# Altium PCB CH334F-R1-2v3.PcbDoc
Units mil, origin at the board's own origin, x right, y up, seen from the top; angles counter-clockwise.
Board outline 3110.24 x 866.14 mil, 2 copper layers (Top Layer, Bottom Layer); 18 components, 20 nets, 108 pads, 313 vias.
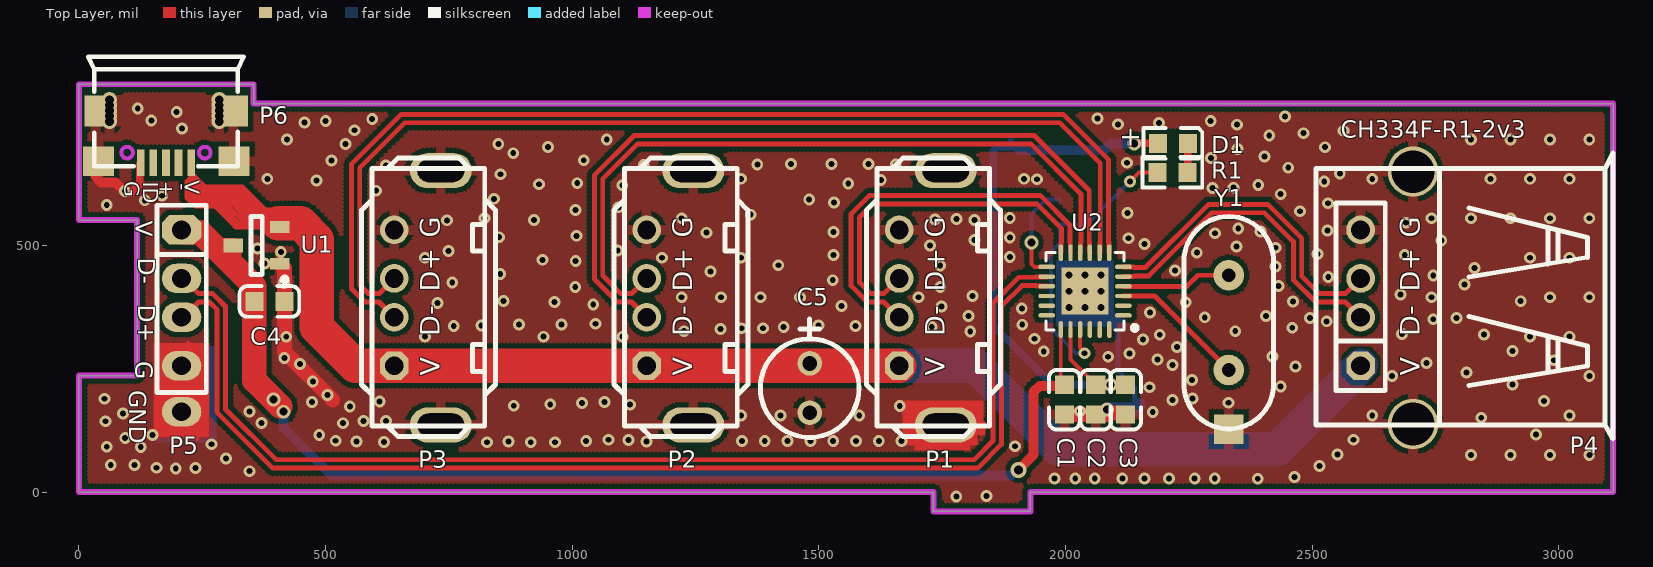
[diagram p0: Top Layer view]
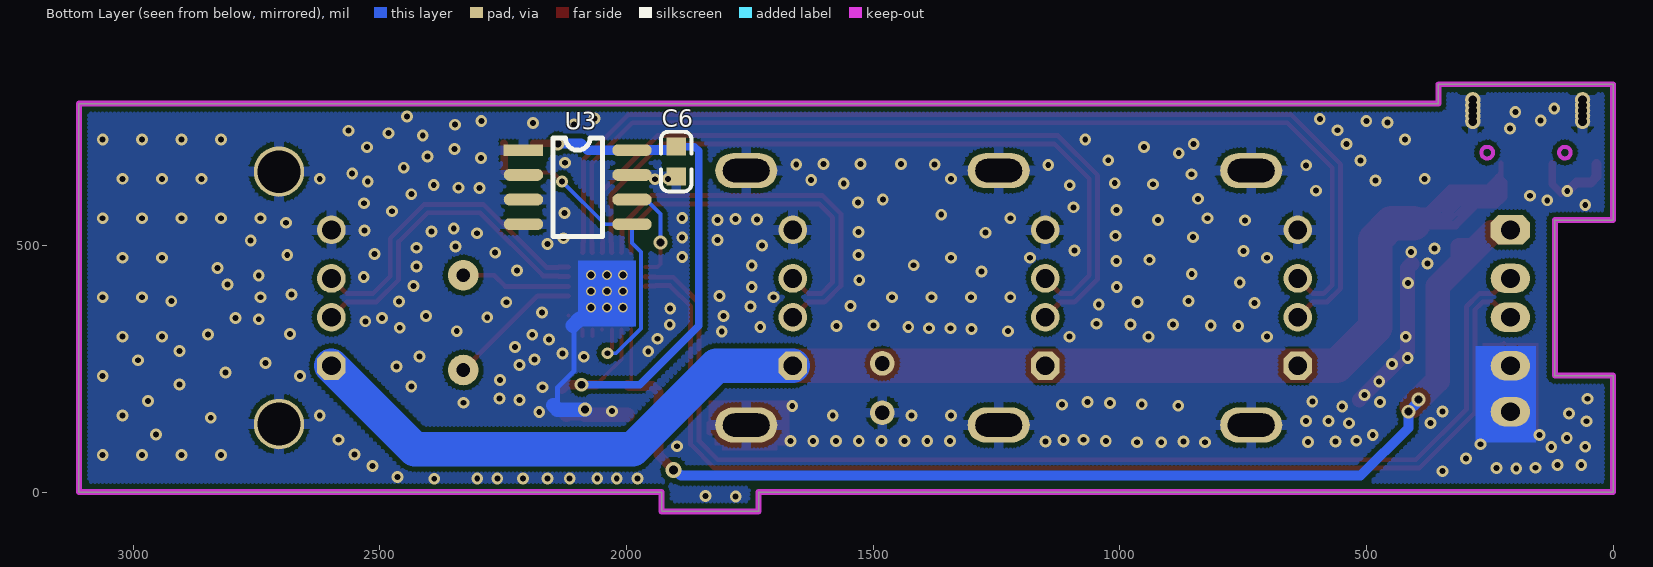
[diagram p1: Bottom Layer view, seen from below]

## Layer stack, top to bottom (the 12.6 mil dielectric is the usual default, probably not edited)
Top Solder: solder mask 0.4, Solder Resist, Dk 3.5
Top Layer: signal copper 1.4
Dielectric 1: dielectric 12.6, FR-4, Dk 4.8
Bottom Layer: signal copper 1.4
Bottom Solder: solder mask 0.4, Solder Resist, Dk 3.5

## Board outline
0,0 0,236.22 118.11,236.22 118.11,551.18 0,551.18 0,826.77 354.33,826.77 354.33,787.4 3110.24,787.4 3110.24,0 1929.13,0 1929.13,-39.37 1732.28,-39.37 1732.28,0

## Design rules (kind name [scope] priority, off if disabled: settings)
Clearance Clearance_1 [InPolygon] p1: gap=10 ignorepadtopadclearanceinfootprint=FALSE
Clearance [All] p2: gap=6 ignorepadtopadclearanceinfootprint=FALSE except(8: Arc-Via Track-Via SMDPad-Via THPad-Via Via-Via Via-Fill Via-Poly Via-Region Via-Hole)
ComponentClearance [All] p1 off: gap=10 collisioncheckmode=3 verticalgap=10 showdistances=FALSE
DiffPairsRouting [All] p1: maxlimit=10 minlimit=7 mostfreqgap=8 toplayer_minwidth=6 toplayer_maxwidth=15 toplayer_prefwidth=8 bottomlayer_minwidth=6 bottomlayer_maxwidth=15 bottomlayer_prefwidth=8 maxuncoupledlength=500
MinimumSolderMaskSliver [All] p1 off: minsoldermaskwidth=10
PolygonConnect PolygonConnect_1 [IsVia] p1: connectstyle=Direct reliefconductorwidth=10 reliefentries=4 polygonreliefangle="90 Angle" airgapwidth=10
PolygonConnect [All] p2: connectstyle=Relief reliefconductorwidth=20 reliefentries=4 polygonreliefangle="90 Angle" airgapwidth=10
RoutingVias [All] p1: holewidth=16 width=28 viastyle="Through Hole" minholewidth=12 minwidth=24 maxholewidth=28 maxwidth=50
SilkToSilkClearance [All] p1 off: silktosilkclearance=10
SilkToSolderMaskClearance [IsPad] p1 off: minsilkscreentomaskgap=10 clearancetoexposedcopper=TRUE
SolderMaskExpansion [All] p1: expansion=4 istentingtop=FALSE
Width [All] p1: maxlimit=100 minlimit=6 preferedwidth=10
25 further rules are at their usual default settings.

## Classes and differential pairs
differential pair UD: +UD_p -UD_n
differential pair UD4: +UD4_p -UD4_n
differential pair UD3: +UD3_p -UD3_n
differential pair UD2: +UD2_p -UD2_n
differential pair UD1: +UD1_p -UD1_n

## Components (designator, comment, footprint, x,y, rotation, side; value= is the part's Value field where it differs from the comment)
C1 "1uF" 0603_C 1997.81,217.54 r270 top
C2 "0.1uF" 0603_C 2061.45,217.54 r270 top
C3 "10uF" 0603_C 2121.9,217.54 r270 top
C4 "10uF" 0603_C 356.1,386.39 r0 top
C5 "220uF" CD0.1 1481.53,260.82 r270 top
C6 "NC(1uF)" 0603_C 1899.27,700.37 r270 bottom
D1 "LED" 0603+ 2188.05,706.74 r0 top
P1 "USB" USB2.0-A-F-TH_4P-V_13.7mm 1662.83,255.91 r180 top
P2 "USB" USB2.0-A-F-TH_4P-V_13.7mm 1151.02,255.91 r180 top
P3 "USB" USB2.0-A-F-TH_4P-V_13.7mm 639.21,255.91 r180 top
P4 "USB" USBAF#1 2598.25,255.91 r90 top
P5 "USB" USBAF#2 208.21,531.5 r270 top
P6 "PowerSupply" USBMICROB-02-GXPX-A1T2 227.66,667.45 r180 top
R1 "1K" 0603_R 2216.99,648.17 r0 top
U1 "CH213K" SOT-23-3 407.15,462.5 r90 top
U2 "CH334F" QFN24_4X4 2039.71,407.29 r90 top
U3 "NC(24C02)" SOIC-8_150mil 2208.98,692.96 r270 bottom
Y1 "12M" XT_AT49 2330.98,247.39 r0 top

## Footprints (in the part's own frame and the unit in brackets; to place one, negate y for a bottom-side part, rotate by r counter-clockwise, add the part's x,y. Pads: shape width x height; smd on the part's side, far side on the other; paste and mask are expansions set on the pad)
0603+ [mm]
  rect 0.93x0.98 smd: 1(0,0) 2(1.54,0)
  silkscreen extent -0.76,-0.79 2.27,0.79
0603_C [mm]
  rect 0.93x0.98 smd: 1(0,0) 2(1.54,0)
  silkscreen extent -0.76,-0.79 2.31,0.79
0603_R [mm]
  rect 0.93x0.98 smd: 1(-0.77,0) 2(0.77,0)
  silkscreen extent -1.53,-0.79 1.54,0.79
CD0.1 [mil]
  round 50 hole 30: 1(0,0) 2(100,0)
  silkscreen extent -90,-100 150,100
QFN24_4X4 [mil]
  round 20 hole 14: 0(-33.21,-32.4) 0(-33.21,32.2) 0(-0.21,-0.1) 0(32.79,-32.4) 0(32.79,32.2)
  rect 95x95 smd mask+2: 0(0,0)
  oval 9x34 smd mask+2: 1(-49.21,-77.8) 2(-29.53,-77.8) 3(-9.84,-77.8) 4(9.84,-77.8) 5(29.53,-77.8) 6(49.21,-77.8) 13(49.21,77.8) 14(29.53,77.8) 15(9.84,77.8) 16(-9.84,77.8) 17(-29.53,77.8) 18(-49.21,77.8)
  oval 34x9 smd mask+2: 7(77.8,-49.21) 8(77.8,-29.53) 9(77.8,-9.84) 10(77.8,9.84) 11(77.8,29.53) 12(77.8,49.21) 19(-77.8,49.21) 20(-77.8,29.53) 21(-77.8,9.84) 22(-77.8,-9.84) 23(-77.8,-29.53) 24(-77.8,-49.21)
  silkscreen extent -79,-106 78,79
SOIC-8_150mil [mil]
  rect 24x80 smd: 1(0,0)
  oval 24x80 smd: 2(50,0) 3(100,0) 4(150,0) 5(150,220) 6(100,220) 7(50,220) 8(0,220)
  silkscreen extent -25,60 175,160
SOT-23-3 [mm] "SOT-23-3"
  rect 0.6x1 smd: 1(0,0) 2(1.9,0)
  rect 0.7x1 smd: 3(0.95,2.4)
  silkscreen extent -0.93,-0.38 2.45,1.49
USB2.0-A-F-TH_4P-V_13.7mm [mm]
  oval 3.2x1.8 hole 1.2 slot 2.4 at 0 deg: 0(-2.4,3.05) 0(-2.4,-10.05)
  oct 1.473x1.473 hole 0.965: 1(0,0)
  round 1.473 hole 0.965: 2(0,-2.5) 3(0,-4.5) 4(0,-7)
  silkscreen extent -5.21,-10.71 1.69,3.65
USBAF#1 [mm]
  round 2.6 hole 2.2: 0(-3,-2.7) 0(10,-2.7)
  oct 1.473x1.473 hole 0.965: 1(0,0)
  round 1.473 hole 0.965: 2(2.5,0) 3(4.5,0) 4(7,0)
  silkscreen extent -3.75,-12.99 10.95,2.29
USBAF#2 [mm]
  oct 1.524x2.032 hole 0.965: 1(0,0)
  oval 1.524x2.032 hole 0.965: 2(2.5,0) 3(4.5,0) 4(7,0)
  silkscreen extent -1.27,-1.27 8.38,1.27
USBMICROB-02-GXPX-A1T2 [mm]
  rect 1.6x1.5 smd: 0(-2.203,-0.083) 0(4.769,-0.083)
  rect 1.5x1.6 smd: 0(-2.167,-2.675)
  round 0.8 hole 0.45: 0(-1.442,-2.134) 0(-1.442,-3.243) 0(-1.442,-2.966) 0(-1.442,-2.689) 0(-1.442,-2.411) 0(4.208,-2.689) 0(4.208,-2.411) 0(4.208,-2.134) 0(4.208,-3.243) 0(4.208,-2.966)
  rect 1.1x1.6 smd: 0(4.933,-2.675)
  rect 0.4x1.35 smd mask+0.051: 1(0,0) 2(0.65,0) 3(1.3,0) 4(1.95,0) 5(2.6,0)
  Keep-Out Layer circle w0.203: c3.3,-0.525 r0.3
  Keep-Out Layer circle w0.203: c-0.7,-0.525 r0.3
  silkscreen extent -2.7,-5.46 5.3,0.17
XT_AT49 [mil]
  rect 60x60 smd: 0(0.03,-119.99)
  round 62 hole 28: 1(0,0) 2(0,192.13)
  silkscreen extent -91,-119 91,311

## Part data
C1 C2 C3 C4 C5 C6: library part CAP, "Capacitor"
D1: "Typical INFRARED GaAs LED"
P1 P2 P3 P4 P5: "USB Port"
P6: library part MicroUSB, "MicroUSB Port"
R1: library part RES
U1: "Ideal Diode 5V*1A"
U2: "4 ports High-Speed USB MTT Hub with over current detect & power control"
U3: library part 24C01
Y1: library part XTAL, "Crystal Oscillator"

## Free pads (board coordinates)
  oval 80x60 hole 38: ""(208.21,162.81)

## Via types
v1: diameter 24, hole 12, Top Layer to Bottom Layer, tented both sides, 302 vias
v2: diameter 28, hole 16, Top Layer to Bottom Layer, tented both sides, 6 vias
v3: diameter 20, hole 14, Top Layer to Bottom Layer, tented both sides, 4 vias
v4: diameter 32, hole 18, Top Layer to Bottom Layer, tented both sides, 1 vias

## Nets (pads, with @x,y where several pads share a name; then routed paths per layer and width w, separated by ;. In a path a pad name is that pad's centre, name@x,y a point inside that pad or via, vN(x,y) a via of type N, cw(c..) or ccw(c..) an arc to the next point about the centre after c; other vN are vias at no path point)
3V3: C2.1 C3.1 C6.1 D1.1 U2.20 U3.8 | length 1212.2
  Top Layer w8: U2.20 2010.37,329.29 2010.37,268.62 2046.15,232.84 2046.15,231.85 C2.1@2047.14,231.85 ; C2.1@2047.14,231.85 C2.1 C2.1@2047.14,231.85
  Top Layer w15: v2(2139.55,706.74) D1.1
  Top Layer w20: C2.1 v2(2091.61,217.54) C3.1 C3.1@2130.21,209.24
  Bottom Layer w15: C6.1@1888.78,709.88 1888.78,701.67 1887.48,700.37 1862.32,700.37 1853.53,691.59 1853.53,336.86 1972.85,217.54 v2(2091.61,217.54)
  Bottom Layer w20: C6.1 1905.92,693.72 1957.39,693.72 U3.8@1987.9,693.72 ; U3.8 2078.06,692.96 2091.84,706.74 v2(2139.55,706.74)
5V: C1.1 C4.1 P5.1 U1.3 U2.19 | length 2493.6
  Top Layer w8: U2.19 1990.5,224.86 C1.1
  Top Layer w20: v2(415,163) 415.37,163 v2@422.95,170.59 ; v4(1905,45) 1935.54,75.54 1935.54,203.42 1947.25,215.13 1995.4,215.13 C1.1
  Top Layer w30: 282.85,499.91 U1.3 313.69,499.9 314.91,498.68 314.91,463.33
  Top Layer w50: P5.1 212.86,526.85 246.01,526.85 355.63,417.23 355.63,226.31 v2@407.93,174.01
  Bottom Layer w20: v2(394.44,187.5) 395.97,185.97 395.97,182.03 v2(415,163) 415,130.2 511.85,33.35 1890.1,33.35 1901.75,45 v4(1905,45)
GND: C1.2 C2.2 C3.2 C4.2 C5.2 C6.2 P1.0 P1.4 P2.0 P2.4 P3.0 P3.4 P4.0 P4.4 P5.4 P6.0 P6.5 pad. U1.1 U2.0 U3.1 U3.2 U3.3 U3.4 U3.7 Y1.0 | length 1884.7
  Top Layer w8: 220.81,208.41 220.81,302.53 ; 222,112.53 222,206.65 ; 225,112.53 225,206.65 ; 227.09,204.87 227.09,299 ; 230,111.08 230,205.21 ; 233,204.17 233,298.3 ; 234,111.08 234,205.21 ; 240,107.99 240,295.21 ; 1834.11,119.74 1834.11,140.29
  Top Layer w15: 104.84,605.5 123.71,624.36 P6.5@123.71,665.85
  Top Layer w20: P6.0@33.46,665 33.46,639.41 45.12,627.76 74.35,627.76 91.94,610.17 v1(93.02,610.17)
  Top Layer w30: U1.1 408.65,462.5 416.73,454.42 C4.2 416.73,284.82 514.65,186.9 ; C1.2 C2.2 v2@2083.96,156.91 ; v2@2083.96,160.06 2118.76,160.06 C3.2
  Bottom Layer w10: U2.0@2039.78,402.6 2072.11,370.27 2091.54,350.84 2106.8,335.58 2106.8,245.19 2139.81,212.19 2139.81,167.06 ; v2(2083.96,167.06) v2@2083.96,169.37
  Bottom Layer w30: U2.0@2072.11,374.08 2072.11,370.27 2072.11,362.52 2083.79,350.84 2091.54,350.84 2095.35,350.84 2108.7,337.49 ; v2(2083.96,167.06) 2139.81,167.06 2148.69,175.95
  other v1: 1778.73,-8.71 1840.22,-8.03 2389.86,26.95 1977.78,27.84 2019.86,27.84 2059.43,27.84 2115.25,27.84 2160.41,27.84 2210.19,27.84 2262,27.84 2302.63,27.84 2464.24,30.58 345.77,42.29 196.36,47.86 157.58,49.29 236.59,48.81 2514.7,52.91 64.67,55.04 112.56,54.56 298,68.06 2822,75 2902,75 2982,75 3062,75 2551.51,75.81 125.49,91.43 56.53,91.91 1897.91,92.85 269.09,96.97 618.87,101.5 827.57,100.98 916.07,100.98 965.42,100.98 563.05,102.8 870.97,102.68 1150.93,102.68 1344.12,103.19 1390.38,103.19 1436.63,103.19 1482.89,103.19 1529.14,103.19 1575.4,103.19 1621.65,103.19 1667.91,103.19 520.64,104.1 1028.39,103.53 1114.34,105.23 1073.49,106.08 2584.23,106.08 93.89,109.63 149.43,115.38 487.31,115.35 2953.66,116.98 370.18,139.83 535.35,139.58 54.14,143.63 576.89,143.91 622.77,143.91 2842.89,150.73 1342,155 1422,155 1582,155 2622,155 3022,155 89.58,159.43 2176.96,162.23 345.61,163.53 2029.63,163.91 549.2,173.34 1664.05,174.13 881.63,174.96 1117.55,177.16 955.63,177.89 1020.11,180.82 2330.39,181.01 1065.53,182.28 472.28,182.92 609.78,183.72 2970.04,184.47 2216.8,186.53 51.74,189.12 2257.28,189.87 504.33,197.02 2170.22,212.45 2436.35,213.77 2906.47,218.22 474.21,223.93 2256.41,227.06 2662,235 3062,235 2813.04,242.58 2466.61,254.53 2216.8,257.36 448.57,259.82 2732.05,261.79 2990.27,267.24 2186.83,268.8 416.43,271.67 2086.65,274.28 2419.56,275.03 2129.63,280.79 1956.07,285.3 2906.47,285.71 2226.06,294.41 2157.41,309.12 1937.53,310.77 420.38,314.93 702,315 942,315 1102,315 2942,315 3022,315 2191.2,318.87 2848.67,319.45 2681.97,320.55 1226.76,326.1 1807.05,325.77 2344.2,326.16 1300.83,330.59 1343.48,332.09 1386.87,332.09 2459.82,333.02 1428.77,334.33 1729.02,334.29 760.01,336.88 1574.67,336.58 815.69,337.61 1499.1,338.08 1912.34,339.28 891.89,339.81 978.34,339.81 1047.21,341.27 2529.59,346.11 2745.54,350.41 2495.56,353.03 2792.74,353.2 2282.31,354.29 1803.79,356.93 2406.72,357.22 2171.5,363.82 1911.51,371.94 1749.02,376.08 1545.74,376.85 1042.82,380.11 727.04,383.04 964.42,385.23 2243.73,384.83 2461.54,386.48 861.12,387.43 2922.84,386.94 1222,395 1302,395 1382,395 1462,395 1702,395 2742,395 2982,395 3062,395 1811.48,397.65 2679.08,400.49 1006.25,415.39 1746.14,415.53 2431.86,417.55 2809.11,420.69 415.57,423.72 756.97,424.97 1528.18,429.51 2532.67,435.86 2745.54,439.02 854.15,442.08 1280.14,447.3 2221.76,448.89 2829.34,454.43 2425.93,456.98 1746.14,459.32 1417.86,459.82 376.59,463.37 1007.16,468.13 939.67,470.84 702,475 1182,475 1342,475 2942,475 3022,475 1887.16,476.48 2687.75,480.44 1529.98,480.68 2511.25,482.86 2266.27,485.27 409.35,486.84 749.2,488.72 1092.03,489.51 362.14,494.06 2425.93,495.35 2346.44,497.74 1725.48,499.88 2160.48,502.83 2761.91,510.3 1815.86,510.79 2128.08,514.59 1887.16,515.96 851.82,516.71 1009,519.49 2303.13,524.72 1272.17,525.84 1529.98,527.32 2395.58,528 2531.26,530.47 2350.37,534.58 2690.64,545.94 746.09,550.91 922.56,551.69 1735.63,552.2 1815.86,551.8 1779.03,553.42 822,555 1222,555 1887.16,555.45 2742,555 2822,555 2902,555 2982,555 3062,555 1362.09,562.26 2125.62,565.59 2475.17,569.23 1006.71,571.47 1093.71,577.24 56.52,582.14 2531.95,585.51 1530.58,587.28 133.59,591.4 1480.46,592.99 841.71,594.45 168.18,600.66 2436.36,603.88 602.29,610.91 2297.76,616.36 2340.73,617.05 1101.53,621.94 2390.91,622.82 932.67,623.99 1559.66,625.44 1010.25,626.12 2524.65,629.78 481.91,631.79 1625.68,632.71 1941.98,634.08 382,635 1342,635 1916.16,635 2622,635 2862,635 2942,635 3022,635 854.93,644.21 2556.15,645.98 2451.69,657.58 622.24,662.42 1145.12,662.73 1375.3,663.89 1655.97,663.89 1443.81,664.72 1525.54,664.72 1600.66,664.72 2124.57,667.64 512.24,672.46 1023.41,672.66 2295.1,677.34 2403.5,680.53 880.58,686.96 2348.53,695.62 951.33,699.4 2526.2,699.11 540.34,705.78 850.26,705.62 422,715 1070.19,714.85 2822,715 2902,715 2982,715 3062,715 2413.15,722.66 2482.48,727.5 559.03,733.42 2563.44,732.6 209.17,737.14 2348.1,744.74 2106.8,745.52 2189.58,748.45 457.39,749.48 500.31,752.44 2294.4,752.41 146.87,753.14 594.64,756.14 2064.71,756.96 2444.72,761.4 198.29,770.28 119.32,777.75
  other v3: 2039.81,374.08 2007.51,407.08 2072.11,407.08 2039.81,440.08
NetD1_2: D1.2 R1.2 | length 59.1
  Top Layer w15: R1.2 2247.99,648.86 2247.99,706.05 D1.2
NetU2_3: U2.3 Y1.1 | length 275.6
  Top Layer w10: U2.3 2180.93,397.45 Y1.1
NetU2_4: U2.4 Y1.2 | length 222.7
  Top Layer w10: U2.4 2246.22,417.13 2268.61,439.52 Y1.2
RST: U2.16
SCL: U2.13 U3.6 | length 203.7
  Top Layer w8: v2(1931.4,505.84) 1931.4,462.49 1937.39,456.5 U2.13
  Bottom Layer w8: v2(1931.4,505.84) 1931.4,563.4 1960.95,592.96 U3.6
SDA: R1.1 U2.21 U3.5 | length 600.3
  Top Layer w8: U2.21 2029.87,291.74 2038.5,283.11 2038.45,283.06 v1(2038.45,281.4) ; v1(2130.65,629.85) 2148.96,648.17 R1.1
  Bottom Layer w8: v1(2038.45,281.4) 2021.06,281.4 1970.77,331.7 1970.77,486.9 1988.98,505.11 U3.5 2043.75,542.96 v1(2130.65,629.85)
UD1_n: P1.2 U2.11 | length 810.3
  Top Layer w10: P1.2 1631.96,385.2 1598.32,385.2 1565.48,418.04 1565.48,563.91 1602.93,601.37 1949,601.37 2008.84,541.53 2008.84,506.83 2009.68,505.98 2009.68,485.59 U2.11
UD1_p: P1.3 U2.12 | length 725.8
  Top Layer w10: P1.3 1631.96,402.2 1605.36,402.2 1582.48,425.09 1582.48,556.87 1609.97,584.37 1941.96,584.37 1991.84,534.48 1991.84,506.83 1991,505.98 1991,485.59 U2.12
UD2_n: P2.2 U2.9 | length 1557.8
  Top Layer w10: P2.2 1120.15,385.2 1091.69,385.2 1045,431.89 1045,642.04 1125.69,722.73 1936.76,722.73 2048.21,611.28 2048.21,506.83 2049.05,505.98 2049.05,485.59 U2.9
UD2_p: P2.3 U2.10 | length 1473.3
  Top Layer w10: P2.3 1120.15,402.2 1098.73,402.2 1062,438.93 1062,635 1132.73,705.73 1929.72,705.73 2031.21,604.24 2031.21,506.83 2030.37,505.98 2030.37,485.59 U2.10
UD3_n: P3.2 U2.7 | length 2166.8
  Top Layer w10: P3.2 608.34,385.2 579.97,385.2 552.41,412.76 552.41,664.45 653.57,765.61 1995.3,765.61 2087.58,673.33 2087.58,506.83 2088.42,505.98 2088.42,485.59 U2.7
UD3_p: P3.3 U2.8 | length 2082.3
  Top Layer w10: P3.3 608.34,402.2 587.01,402.2 569.41,419.8 569.41,657.41 660.61,748.61 1988.25,748.61 2070.58,666.28 2070.58,506.83 2069.74,505.98 2069.74,485.59 U2.8
UD4_n: P4.2 U2.5 | length 667.4
  Top Layer w10: U2.5 2118.01,437.32 2138.41,437.32 2139.25,438.16 2169.12,438.16 2297.19,566.23 2403.34,566.23 2462.04,507.54 2462.04,430.28 2507.11,385.2 2567.38,385.2 P4.2
UD4_p: P4.3 U2.6 | length 667.4
  Top Layer w10: U2.6 2118.01,456 2138.41,456 2139.25,455.16 2162.08,455.16 2290.15,583.23 2410.39,583.23 2479.04,514.58 2479.04,437.32 2514.15,402.2 2567.38,402.2 P4.3
UD_n: P5.2 U2.14 | length 2345.5
  Top Layer w10: P5.2 211.83,433.07 242.7,402.2 271.31,402.2 297.25,376.26 297.25,168.13 399.94,65.44 1814.85,65.44 1853.11,103.71 1853.11,383.37 1905.21,435.47 1940.17,435.47 1941.02,436.32 1961.41,436.32 U2.14
UD_p: P5.3 U2.15 | length 2345.5
  Top Layer w10: P5.3 211.83,354.33 242.7,385.2 264.27,385.2 280.25,369.22 280.25,161.09 392.9,48.44 1821.89,48.44 1870.11,96.67 1870.11,376.33 1912.25,418.47 1940.17,418.47 1941.02,417.63 1961.41,417.63 U2.15
VBUS: C5.1 P1.1 P2.1 P3.1 P4.1 P6.1 U1.2 | length 4419.3
  Top Layer w10: 247.13,591.38 252.13,591.38 ; 252.85,603.63 251.45,605.02 ; 252.85,608.63 252.85,605.02 ; 254.37,584.14 259.37,584.14 ; 339.62,561.86 345.62,561.86 ; U1.2@404.02,544.78 336.98,544.78 ; 404.02,553.86 340.88,553.86 310.6,584.14 259.37,584.14 ; U1.2 318.44,537.3 310.96,544.78 ; 407.15,571.39 378.91,571.39 ; 408.32,561.86 345.62,561.86 ; 219.15,602.21 241.73,579.63 ; 219.15,602.21 219.15,629.22 226.76,636.83 226.76,666.54 P6.1 P6.1@227.66,646.78 ; 219.15,602.21 219.15,597.21 236.73,579.63 241.73,579.63 ; 227.66,615.85 227.66,619.83 ; 227.66,615.85 227.66,604.47 252.5,579.63 ; 227.66,615.85 238.49,605.02 ; 227.66,619.83 227.66,628.81 ; 227.66,619.83 242.47,605.02 ; 227.66,628.81 P6.1@227.66,646.78 ; 227.66,628.81 251.45,605.02 ; P6.1@227.66,646.78 234.14,640.3 ; 234.14,640.3 255.44,619 ; 234.14,640.3 234.14,633.09 255.74,611.49 ; 238.49,605.02 252.13,591.38 ; 238.49,605.02 242.47,605.02 ; 241.73,579.63 252.5,579.63 ; 242.47,605.02 251.45,605.02 ; 242.47,605.02 247.47,600.02 257.85,600.02 ; 251.45,605.02 252.85,605.02 ; 252.13,591.38 266.49,591.38 ; 252.13,591.38 259.37,584.14 ; 252.5,579.63 263.88,579.63 ; 252.85,605.02 257.85,600.02 ; 252.85,605.02 262.21,605.02 ; 255.44,619 302.05,619 ; 255.44,619 262.95,611.49 ; 255.74,611.49 262.21,605.02 ; 255.74,611.49 262.95,611.49 ; 257.85,600.02 267.21,600.02 ; 257.85,600.02 266.49,591.38 ; 259.37,584.14 263.88,579.63 ; 262.21,605.02 269.41,605.02 ; 262.21,605.02 267.21,600.02 ; 262.95,611.49 309.55,611.49 ; 262.95,611.49 269.41,605.02 ; 263.88,579.63 276.12,579.63 ; 266.49,591.38 316.1,591.38 345.62,561.86 ; 267.21,600.02 274.41,600.02 ; 269.41,605.02 316.02,605.02 ; 269.41,605.02 274.41,600.02 ; 274.41,600.02 321.02,600.02 ; 276.12,579.63 288.35,579.63 ; 276.12,579.63 310.96,544.78 ; 288.35,579.63 302.14,579.63 336.98,544.78 ; 288.35,579.63 323.2,544.78 ; 302.05,619 311.96,619 ; 302.05,619 309.55,611.49 ; 309.55,611.49 319.46,611.49 ; 309.55,611.49 316.02,605.02 ; 310.96,544.78 323.2,544.78 ; 311.96,619 319.48,619 ; 311.96,619 319.46,611.49 ; 316.02,605.02 325.93,605.02 ; 316.02,605.02 321.02,600.02 ; 319.46,611.49 325.93,605.02 ; 319.48,619 331.3,619 378.91,571.39 ; 319.48,619 367.08,571.39 ; 321.02,600.02 349.66,571.39 359.57,571.39 ; 323.2,544.78 336.98,544.78 ; 325.93,605.02 359.57,571.39 ; 359.57,571.39 367.08,571.39 ; 367.08,571.39 378.91,571.39
  Top Layer w70: U1.2@404.02,544.78 449.4,544.78 482.34,511.84 482.34,333.82 560.26,255.91 P3.1 P2.1 P1.1
  Bottom Layer w70: P1.1 1818.24,255.91 1987.3,86.84 2429.18,86.84 P4.1
pads on no net: P6.2 P6.3 P6.4 U2.1 U2.2 U2.17 U2.18 U2.22 U2.23 U2.24
copper on no net: | length 27.1
  Top Layer w8: 2049.55,329.49 2049.74,329.29 ; 2069.24,329.49 2069.43,329.29 2069.43,315.97 ; 2088.92,329.49 2089.25,329.16 2089.25,316.66 ; 2117.51,358.08 2117.71,357.88

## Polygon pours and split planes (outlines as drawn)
GND on Bottom Layer "GND" (hatched 90Degree grid 8 track 8, remove dead copper, pour order 1): 0,826.77 0,551.18 118.11,551.18 118.11,236.22 0,236.22 0,0 1732.28,0 1732.28,-39.37 1929.13,-39.37 1929.13,0 3110.24,0 3110.24,787.4 354.33,787.4 354.33,826.77
GND on Top Layer "GND" (hatched 90Degree grid 8 track 8, remove dead copper, pour order 0): 0,826.77 0,551.18 118.11,551.18 118.11,236.22 0,236.22 0,0 1732.28,0 1732.28,-39.37 1929.13,-39.37 1929.13,0 3110.24,0 3110.24,787.4 354.33,787.4 354.33,826.77

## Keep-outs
Keep-Out Layer:
  the board outline again, w12

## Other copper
Top Layer:
  rectangle net GND: 1694,84.44 1806,101.7
  rectangle net GND: 1668.7,94.34 1822.2,119.42
  rectangle net GND: 1669.7,115 1834.11,185.26
  rectangle net GND: 151.31,111.08 265.24,302.38
Bottom Layer:
  rectangle net GND: 1980.77,335.84 2098.79,469.37
  rectangle net GND: 156.56,100.86 278.7,295.9

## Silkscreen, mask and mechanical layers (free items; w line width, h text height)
Top Overlay:
  text "CH334F-R1-2v3" at 2557.63,717.88 h35
  text "GND" at 102.23,206.83 h35 r270
Mechanical 1:
  lines w10: 0,0 0,236.22 118.11,236.22 118.11,551.18 0,551.18 0,787.4 0,826.77 354.33,826.77 354.33,787.4 3110.24,787.4 3110.24,0 1929.13,0 1929.13,-39.37 1732.28,-39.37 1732.28,0 0,0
